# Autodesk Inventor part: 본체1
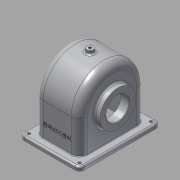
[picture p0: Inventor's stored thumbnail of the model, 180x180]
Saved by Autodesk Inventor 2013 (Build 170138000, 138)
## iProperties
Created: 2016-01
Part Number: 본체1
Material: 알루미늄 6061
Document SubType Name: Modeling
Designer: dgall
Density: 2.71 g/cm^3
Mass: 767.79 g
Surface Area: 1005.63 cm^2
Volume: 283.317 cm^3
Author: dgall
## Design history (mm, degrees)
sketch "스케치3"
  geometry: L1 (38.5, -57)-(-38.5, -57); L2 (-38.5, -57)-(-38.5, 57); L3 (-38.5, 57)-(38.5, 57); L4 (38.5, 57)-(38.5, -57); L5 (38.5, -57)-(-38.5, 57); L6 (-38.5, -57)-(38.5, 57); 1 further point
  constraints: 12 end point, 2 midpoint, 2 parallel, 1 horizontal, 1 perpendicular
  dimensions: "d4" = 77 distance of L2.end L3.end; "d6" = 114 distance of L3.end L1.start
extrude "돌출1" new body sketch "스케치3" distance "d7" = 114; taper "d8" = 0 deg
feature "쉘1" dims "d10" = 6
sketch "스케치9"
  geometry: L1 (38.5, -57)-(38.5, 57) reference; L2 (38.5, 57)-(-38.5, 57) reference; L3 (-33.5, -52)-(33.5, -52); L4 (33.5, -52)-(33.5, 52); L5 (33.5, 52)-(-33.5, 52); L6 (-33.5, 52)-(-33.5, -52); L7 (-33.5, -52)-(33.5, 52); L8 (33.5, -52)-(-33.5, 52); 1 further point
  constraints: 12 end point, 2 midpoint, 2 parallel, 1 horizontal, 1 perpendicular
  dimensions: "d28" = 5 distance between parallel lines of L5 L2; "d29" = 5 distance between parallel lines of L1 L4
extrude "돌출4" cut sketch "스케치9" stored distance "d30" = 7; taper "d31" = 0 deg
fillet "모깎기4" dims "d32" = 57
fillet "모깎기5" dims "d33" = 51
fillet "모깎기6" dims "d34" = 9
fillet "모깎기7" dims "d35" = 14
sketch "스케치10"
  geometry: L1 (-33.5, -43)-(-33.5, 43) reference; L2 (-24.5, 52)-(24.5, 52) reference; L3 (33.5, 43)-(33.5, -43) reference; L4 (24.5, -52)-(-24.5, -52) reference; L5 (-52, -70)-(52, -70); L6 (52, -70)-(52, 70); L7 (52, 70)-(-52, 70); L8 (-52, 70)-(-52, -70); L9 (-52, -70)-(52, 70); L10 (52, -70)-(-52, 70); A1 r 9 centre (-24.5, 43) between (-24.5, 52) and (-33.5, 43) reference; A2 r 9 centre (24.5, 43) between (33.5, 43) and (24.5, 52) reference; A3 r 9 centre (24.5, -43) between (24.5, -52) and (33.5, -43) reference; A4 r 9 centre (-24.5, -43) between (-33.5, -43) and (-24.5, -52) reference; 1 further point
  constraints: 12 end point, 2 midpoint, 2 parallel, 1 horizontal, 1 perpendicular
  dimensions: "d36" = 140 distance of L5.end L6.end; "d38" = 104 distance of L6.end L7.end
extrude "돌출5" join sketch "스케치10" distance "d39" = 7; taper "d40" = 0 deg
node "작업 평면2"
sketch "스케치11"
  geometry: L1 (63, 43)-(63, 0) reference; L2 (63, 0)-(63, -57) reference; L3 (-27.5, -64)-(76.5, -64) reference; L4 (24.5, -64)-(24.5, -4); L5 (-14.937, -4)-(81.52, -4); L6 (63, 27)-(73, 27); L7 (73, 27)-(73, -4); L8 (-14, 0)-(-14, 43) reference; L9 (63, 27)-(63, -4); 1 further point
  constraints: 10 end point, 5 point on line, 3 perpendicular, 1 midpoint, 1 parallel
  dimensions: "d41" = 60 distance of L4.start L4.end; "d44" = 62 diameter of L6 L5; "d45" = 87 distance between parallel lines of L7 L8
revolve "회전1" sketch "스케치11" stored, may be unused: angle "d46" = 90 deg
sketch "스케치12"
  geometry: C1 r 31 at (0, 0) reference; C2 r 20 at (0, 0); 1 further point
  constraints: 1 centre point, 1 coincident
  dimensions: "d47" = 40 diameter of C2
extrude "돌출6" cut sketch "스케치12" stored distance "d49" = 10; taper "d50" = 0 deg
sketch "스케치13"
  geometry: L1 (-14, 0)-(-14, 43) reference; L2 (-9, 42)-(-9, 0) reference; L3 (-9, 0)-(-9, -64) reference; L4 (-14, -57)-(-14, 0) reference; L5 (-27.5, -64)-(76.5, -64) reference; L6 (24.5, -64)-(24.5, -4); L7 (-24.667, -4)-(93.332, -4); L8 (-9, 35.747)-(5, 24); L9 (5, 24)-(5, -4); L10 (-14, 33.416)-(-11, 30.899); L11 (-11, 30.899)-(-11, -4); L12 (-9, 35.747)-(-9, -4); 1 further point
  constraints: 14 end point, 7 point on line, 4 perpendicular, 1 midpoint, 1 parallel
  dimensions: "d51" = 60 distance of L6.start L6.end; "d53" = 50 deg angle of L9 L8; "d55" = 56 diameter of L8.end L7; "d56" = 5 distance between parallel lines of L8 L10; "d57" = 3 distance from line of L1 L10.end; "d58" = 16 distance between parallel lines of L9 L11
revolve "회전2" sketch "스케치13" stored, may be unused: angle "d59" = 90 deg
sketch "스케치14"
  geometry: L1 (-27.5, -57)-(76.5, -57) reference; L2 (76.5, -57)-(76.5, -64) reference; L3 (-27.5, -64)-(76.5, -64) reference; L4 (-27.5, -57)-(-27.5, -64) reference; L5 (-27.5, -64)-(76.5, -64) reference; L6 (-9, 35.747)-(-9, -43.747) reference; L7 (5, -32)-(5, 24) reference; L8 (-9, 35.747)-(-9, -43.747) reference; L9 (-14, -57)-(-14, 0) reference; L10 (-14, 0)-(-14, 43) reference; L11 (24.5, -64)-(24.5, -4); L12 (-20.984, -4)-(90.417, -4); L13 (-11, 16)-(5, 16); L14 (-14, 33.416)-(-11, 30.899); L15 (-9, 35.747)-(5, 24) reference; L16 (-11, 30.899)-(-11, -4); L17 (-14, 33.416)-(-14, -4); 1 further point
  constraints: 12 end point, 6 point on line, 3 parallel, 2 perpendicular, 1 midpoint
  dimensions: "d60" = 60 distance of L11.start L11.end; "d63" = 40 diameter of L13 L12; "d66" = 5 distance between parallel lines of L15 L14; "d67" = 3 horizontal distance of L14.start L14.end; "d68" = 16 distance of L13.start L13.end
revolve "회전3" sketch "스케치14" stored, may be unused: angle "d69" = 90 deg
sketch "스케치15"
  geometry: C1 r 34.899 at (0, 0) reference; C2 r 20 at (0, 0); 1 further point
  constraints: 1 centre point, 1 coincident
  dimensions: "d70" = 40 diameter of C2
extrude "돌출7" cut sketch "스케치15" distance "d72" = 16; taper "d73" = 0 deg
fillet "모깎기8" dims "d74" = 3
chamfer "모따기1" distance "d75" = 1; stored, may be unused: second distance "d76" = 2, angle "d77" = 45 deg
sketch "스케치17" dims "d78" = 48
  geometry: L1 (0, 0)-(-24, 0); C1 r 21 at (0, 0) reference; 1 further point
  constraints: 2 end point, 1 coincident, 1 horizontal, 1 horizontal alignment, 2 other
hole "구멍1" sketch "스케치17" at (-24, 0) diameter "d80" = 2.459; stored, may be unused: countersink angle "d84" = 90 deg, drill point angle "d86" = 118 deg; dims "d81" = 6, "d82" = 4, "d83" = 2, "d85" = 8
sketch "스케치18" dims "d90" = 56
  geometry: L1 (0, 0)-(28, 0); C1 r 21 at (0, 0) reference; 1 further point
  constraints: 2 end point, 1 coincident, 1 horizontal, 1 horizontal alignment, 2 other
hole "구멍2" sketch "스케치18" at (28, 0) diameter "d92" = 2.459; stored, may be unused: countersink angle "d96" = 90 deg, drill point angle "d98" = 118 deg; dims "d93" = 7, "d94" = 4, "d95" = 2, "d97" = 9
fillet "모깎기9" dims "d102" = 3
fillet "모깎기10" dims "d103" = 8
fillet "모깎기11" dims "d104" = 3
sketch "스케치20"
  geometry: C1 r 2.5 at (-44, 62); C2 r 2.5 at (44, 62); C3 r 2.5 at (-44, -62); C4 r 2.5 at (44, -62); A1 r 5 centre (-44, -62) between (-49, -62) and (-44, -67) reference; A2 r 5 centre (44, -62) between (44, -67) and (49, -62) reference; A3 r 5 centre (44, 62) between (49, 62) and (44, 67) reference; A4 r 5 centre (-44, 62) between (-44, 67) and (-49, 62) reference; 1 further point
  constraints: 4 centre point, 4 coincident
  dimensions: "d105" = 5 diameter of C1; "d107" = 5 diameter of C2; "d108" = 5 diameter of C3; "d109" = 5 diameter of C4
extrude "돌출8" cut sketch "스케치20" stored distance "d110" = 16; taper "d111" = 0 deg
node "작업 평면4"
sketch "스케치24"
  geometry: C1 r 6 at (0, 0); 1 further point
  constraints: 1 centre point, 1 coincident
  dimensions: "d120" = 12 diameter of C1
extrude "돌출10" join sketch "스케치24" stored distance "d122" = 16; taper "d123" = 0 deg
fillet "모깎기13" dims "d124" = 3
sketch "스케치25"
  geometry: C1 r 6 at (0, 0) reference
hole "구멍3" sketch "스케치25" at (0, 0) diameter "d125" = 4.459; stored, may be unused: countersink angle "d129" = 90 deg, drill point angle "d131" = 118 deg; dims "d126" = 7, "d127" = 4, "d128" = 2, "d130" = 9
sketch "스케치26"
  geometry: L1 (-0.387, -30.398)-(49.387, -30.398); L2 (49.387, -30.398)-(49.387, -37.602); L3 (49.387, -37.602)-(-0.387, -37.602); L4 (-0.387, -37.602)-(-0.387, -30.398); L5 (-0.387, -34)-(49.387, -34); L6 (24.5, -30.398)-(24.5, -37.602); L7 (-14, 0)-(-14, -57) reference; L8 (68.5, -64)-(-19.5, -64) reference; 1 further point
  constraints: 4 end point, 4 midpoint, 2 other
  dimensions: "d132" = 38.5 distance between parallel lines of L7 L6; "d133" = 30 distance between parallel lines of L8 L5
extrude "돌출11" join sketch "스케치26" distance "d134" = 0.5; taper "d135" = 0 deg
fillet "모깎기14" dims "d136" = 1
node "솔리드1"
pattern_circular "원형 패턴1" dims angle "d88" = 360 deg
pattern_circular "원형 패턴2" dims angle "d100" = 360 deg
node "투영된 루프2"
node "투영된 루프3"
other parameters: "d119" = -127
